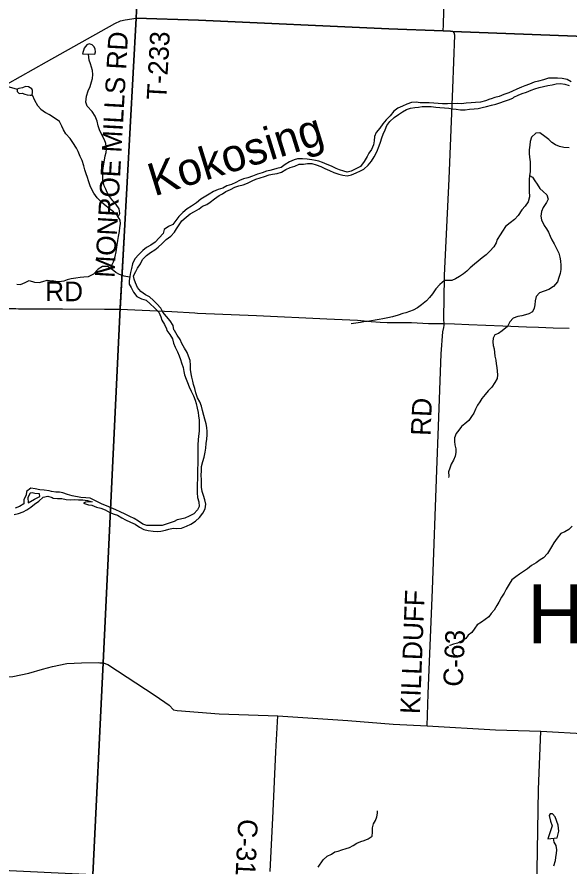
# Model space of a CAD drawing. Extents: x 1759416 to 2214760, y 252598 to 1116833.
# Drawn here: x 2002809 to 2011247, y 856869 to 869846 of the extents above; entities that cross this region are included whole.
import ezdxf

# ---------------------------------------------------------------- set-up
doc = ezdxf.new("R2010")
doc.units = 0
for name, color, linetype in [('GM_X_County_Road', 7, 'Continuous'), ('GM_X_County_Road_Text', 7, 'Continuous'), ('GM_X_Major_River', 7, 'Continuous'), ('GM_X_Major_River_Text', 7, 'Continuous'), ('GM_X_Minor_Lake', 7, 'Continuous'), ('GM_X_Minor_River', 7, 'Continuous'), ('GM_X_State_Location', 7, 'Continuous'), ('GM_X_State_Route', 7, 'Continuous'), ('GM_X_Township', 7, 'Continuous'), ('GM_X_Township_Road', 7, 'Continuous'), ('GM_X_Township_Road_Text', 7, 'Continuous'), ('GM_X_Township_Text', 7, 'Continuous')]:
    doc.layers.add(name, color=color, linetype=linetype)

msp = doc.modelspace()

# ---------------------------------------------------------------- linework, layer by layer
at = {"layer": 'GM_X_County_Road'}
for points in [[(2009323, 869634), (2009327, 869728), (2009333, 869937), (2009380, 871141), (2009401, 871508)], [(2009479, 869618), (2009472, 869626), (2009435, 869627), (2009323, 869634)], [(2009336, 865162), (2009331, 865220), (2009332, 865273), (2009338, 865524), (2009344, 865892), (2009413, 867374), (2009471, 868754), (2009503, 869566), (2009492, 869601), (2009479, 869618)], [(2000444, 865410), (2000489, 865410), (2001258, 865411), (2002106, 865391), (2002792, 865388), (2002830, 865387)], [(2002830, 865387), (2003505, 865384), (2004148, 865379), (2004179, 865379)], [(2004179, 865379), (2004185, 865379), (2004387, 865379)], [(2004387, 865379), (2004387, 865379), (2005176, 865343), (2005525, 865323), (2005570, 865321)], [(2005570, 865321), (2006468, 865283), (2007546, 865232), (2008015, 865211), (2008221, 865194), (2008359, 865180), (2008465, 865178), (2008839, 865174), (2009099, 865163), (2009336, 865162), (2009497, 865154), (2009716, 865144), (2010237, 865123), (2010595, 865109), (2010781, 865103), (2011004, 865095), (2011250, 865088)], [(2009078, 859014), (2009095, 859503), (2009158, 861095), (2009225, 862918), (2009254, 863593), (2009294, 864696), (2009317, 865034), (2009332, 865099), (2009340, 865130), (2009336, 865162)], [(2006678, 856785), (2006723, 857708), (2006764, 858614), (2006795, 859166)]]:
    msp.add_lwpolyline(points, dxfattribs=at)
at = {"layer": 'GM_X_Major_River'}
for points in [[(2011281, 868856), (2011217, 868889), (2011143, 868906), (2011072, 868910), (2011004, 868913), (2010932, 868908), (2010855, 868885), (2010783, 868865), (2010715, 868848), (2010645, 868821), (2010573, 868794), (2010522, 868774), (2010450, 868741), (2010382, 868710), (2010326, 868686), (2010249, 868659), (2010181, 868630), (2010111, 868615), (2010055, 868595), (2010037, 868588)], [(2010389, 868604), (2010403, 868618), (2010469, 868651), (2010533, 868678), (2010596, 868698), (2010666, 868729), (2010724, 868750), (2010792, 868766), (2010858, 868785), (2010924, 868800), (2010989, 868811), (2011053, 868823), (2011119, 868830), (2011183, 868821), (2011250, 868799)], [(2009606, 868520), (2009536, 868521), (2009392, 868520), (2009315, 868517), (2009247, 868522), (2009179, 868529), (2009107, 868531), (2009039, 868532), (2008971, 868535), (2008909, 868543), (2008837, 868540), (2008767, 868511), (2008700, 868482), (2008630, 868454), (2008568, 868405), (2008513, 868336), (2008450, 868273), (2008400, 868211), (2008353, 868144), (2008299, 868079), (2008276, 868021), (2008267, 867953), (2008259, 867893), (2008228, 867822), (2008189, 867762), (2008161, 867711), (2008116, 867635), (2008059, 867562), (2007989, 867527), (2007919, 867488), (2007855, 867472), (2007805, 867487), (2007739, 867510), (2007687, 867532), (2007616, 867563), (2007552, 867593), (2007480, 867624), (2007425, 867641), (2007371, 867653), (2007315, 867662), (2007245, 867672), (2007173, 867677), (2007097, 867676), (2007045, 867664), (2006973, 867631), (2006906, 867590), (2006846, 867547), (2006782, 867529), (2006728, 867514), (2006676, 867499), (2006625, 867487), (2006555, 867466), (2006483, 867443), (2006409, 867413), (2006337, 867386), (2006270, 867371), (2006208, 867346), (2006156, 867316), (2006088, 867287), (2006016, 867264), (2005953, 867231), (2005883, 867207), (2005815, 867178), (2005746, 867137), (2005618, 867060), (2005551, 867003), (2005477, 866952), (2005412, 866911), (2005346, 866858), (2005281, 866798), (2005237, 866737), (2005192, 866675), (2005126, 866642), (2005059, 866597), (2005041, 866535), (2004984, 866468), (2004923, 866405), (2004855, 866356), (2004791, 866324), (2004730, 866277), (2004670, 866216), (2004611, 866150), (2004576, 866075), (2004561, 866003), (2004545, 865940), (2004534, 865880), (2004521, 865814), (2004521, 865764), (2004552, 865710), (2004592, 865640), (2004643, 865575), (2004711, 865539), (2004782, 865518), (2004846, 865461), (2004911, 865399), (2004976, 865336), (2005008, 865262), (2005025, 865210), (2005066, 865146), (2005096, 865081), (2005101, 865054)], [(2009522, 868437), (2009589, 868429), (2009659, 868428), (2009725, 868435), (2009795, 868440), (2009857, 868446), (2009918, 868461), (2009988, 868478), (2010060, 868496), (2010128, 868513), (2010192, 868534), (2010262, 868557), (2010323, 868581), (2010389, 868604)], [(2010037, 868588), (2009971, 868564), (2009896, 868543), (2009820, 868540), (2009750, 868533), (2009676, 868526), (2009606, 868520)], [(2005215, 865054), (2005207, 865064), (2005194, 865130), (2005151, 865203), (2005094, 865269), (2005040, 865332), (2005007, 865394), (2004948, 865464), (2004896, 865513), (2004833, 865567), (2004771, 865600), (2004702, 865648), (2004650, 865713), (2004621, 865783), (2004598, 865839), (2004592, 865889), (2004625, 865955), (2004651, 866006), (2004698, 866072), (2004727, 866137), (2004789, 866199), (2004852, 866246), (2004914, 866287), (2004968, 866326), (2005027, 866386), (2005088, 866445), (2005158, 866496), (2005219, 866557), (2005249, 866607), (2005288, 866670), (2005328, 866732), (2005393, 866785), (2005457, 866838), (2005522, 866872), (2005594, 866915), (2005647, 866956), (2005709, 866982), (2005763, 867015), (2005828, 867066), (2005900, 867115), (2005952, 867143), (2006003, 867176), (2006071, 867211), (2006141, 867245), (2006199, 867264), (2006268, 867281), (2006332, 867308), (2006402, 867340), (2006462, 867367), (2006526, 867386), (2006591, 867408), (2006665, 867431), (2006717, 867444), (2006787, 867453), (2006851, 867475), (2006918, 867514), (2006986, 867545), (2007054, 867566), (2007120, 867596), (2007188, 867597), (2007252, 867606), (2007318, 867606), (2007384, 867587), (2007452, 867558), (2007513, 867532), (2007585, 867499), (2007653, 867468), (2007728, 867444), (2007790, 867427), (2007856, 867418), (2007920, 867432), (2007994, 867463), (2008059, 867494), (2008111, 867522), (2008176, 867583), (2008228, 867642), (2008271, 867708), (2008310, 867787), (2008346, 867875), (2008367, 867930), (2008388, 868000), (2008404, 868056), (2008435, 868121), (2008464, 868185), (2008510, 868250), (2008575, 868309), (2008641, 868355), (2008700, 868394), (2008764, 868431), (2008826, 868452), (2008888, 868464), (2008948, 868469), (2009004, 868475), (2009068, 868478), (2009138, 868475), (2009210, 868468), (2009274, 868462), (2009344, 868457), (2009412, 868452), (2009464, 868444), (2009522, 868437)], [(2005101, 865054), (2005147, 864992), (2005185, 864928), (2005201, 864859), (2005226, 864797), (2005262, 864727), (2005290, 864665), (2005310, 864612), (2005324, 864560), (2005348, 864490), (2005357, 864426), (2005367, 864376), (2005393, 864309), (2005415, 864257), (2005441, 864193), (2005471, 864125), (2005505, 864055), (2005532, 863988), (2005548, 863938), (2005564, 863868), (2005576, 863802), (2005584, 863752), (2005591, 863683), (2005591, 863633), (2005595, 863567), (2005595, 863515), (2005585, 863441), (2005579, 863381), (2005572, 863309), (2005572, 863254), (2005574, 863188), (2005572, 863114), (2005571, 863010), (2005567, 862940), (2005567, 862890), (2005569, 862837), (2005569, 862781), (2005565, 862711), (2005564, 862575), (2005570, 862501), (2005590, 862434), (2005592, 862366), (2005567, 862314), (2005513, 862254), (2005441, 862214), (2005375, 862188), (2005309, 862171), (2005259, 862159), (2005209, 862135), (2005152, 862115), (2005102, 862097), (2005030, 862075), (2004966, 862075), (2004916, 862072), (2004866, 862072), (2004794, 862074), (2004730, 862096), (2004664, 862142), (2004598, 862179), (2004534, 862213), (2004464, 862249), (2004386, 862284), (2004320, 862312), (2004250, 862346), (2004178, 862376), (2004110, 862401), (2004058, 862425), (2003988, 862463), (2003928, 862490), (2003860, 862496), (2003786, 862502), (2003650, 862526), (2003582, 862545), (2003510, 862571), (2003458, 862581), (2003400, 862583), (2003338, 862595), (2003302, 862604)], [(2003344, 862501), (2003362, 862493), (2003430, 862487), (2003496, 862485), (2003558, 862473), (2003620, 862464), (2003686, 862472), (2003748, 862468), (2003814, 862468), (2003886, 862458), (2003956, 862435), (2003855, 862428), (2003825, 862414), (2003904, 862392), (2003955, 862385), (2004024, 862355), (2004090, 862337), (2004158, 862312), (2004228, 862272), (2004292, 862246), (2004346, 862230), (2004412, 862191), (2004468, 862161), (2004546, 862125), (2004614, 862093), (2004682, 862050), (2004748, 862012), (2004816, 861998), (2004890, 861987), (2004956, 861983), (2005010, 861985), (2005078, 862001), (2005132, 862017), (2005198, 862035), (2005252, 862026), (2005322, 862034), (2005399, 862062), (2005467, 862096), (2005537, 862140), (2005599, 862198), (2005649, 862262), (2005684, 862328), (2005694, 862400), (2005682, 862464), (2005658, 862530), (2005640, 862595), (2005631, 862661), (2005627, 862723), (2005627, 862773), (2005625, 862841), (2005627, 862911), (2005631, 862976), (2005650, 863050), (2005672, 863120), (2005684, 863192), (2005694, 863256), (2005701, 863326), (2005709, 863392), (2005717, 863460), (2005715, 863511), (2005711, 863571), (2005699, 863625), (2005680, 863697), (2005666, 863757), (2005646, 863830), (2005628, 863898), (2005602, 863962), (2005570, 864024), (2005545, 864101), (2005529, 864167), (2005507, 864231), (2005495, 864281), (2005481, 864341), (2005471, 864391), (2005462, 864456), (2005462, 864524), (2005456, 864596), (2005432, 864664), (2005408, 864716), (2005371, 864785), (2005331, 864853), (2005301, 864917), (2005255, 864985), (2005215, 865054)], [(2003302, 862604), (2003224, 862612), (2003156, 862621), (2003086, 862635), (2003022, 862643), (2002952, 862591), (2002950, 862539), (2002914, 862471), (2002912, 862404), (2002848, 862364), (2002782, 862341)], [(2003012, 862569), (2002976, 862503), (2002980, 862420), (2003078, 862474)], [(2003078, 862474), (2003156, 862516), (2003152, 862558), (2003082, 862565), (2003040, 862575), (2003012, 862569)], [(2002768, 862244), (2002830, 862258), (2002904, 862284), (2002958, 862312), (2003022, 862356), (2003076, 862398), (2003142, 862448), (2003210, 862506), (2003278, 862524), (2003344, 862501)]]:
    msp.add_lwpolyline(points, dxfattribs=at)
at = {"layer": 'GM_X_Minor_Lake'}
for points in [[(2003997, 869278), (2004007, 869312), (2004005, 869354), (2003989, 869388), (2003959, 869418), (2003914, 869434), (2003878, 869420), (2003837, 869368), (2003811, 869280)], [(2003811, 869280), (2003997, 869278)], [(2003048, 868691), (2003047, 868721), (2003035, 868749), (2002987, 868777), (2002939, 868784), (2002895, 868764), (2002835, 868752), (2002810, 868740), (2002814, 868706), (2002844, 868678), (2002888, 868680), (2002930, 868664), (2002966, 868655), (2003012, 868651)], [(2003012, 868651), (2003029, 868650), (2003043, 868654), (2003048, 868691)], [(2011067, 857302), (2011093, 857402), (2011079, 857495), (2011036, 857619), (2010996, 857669), (2010960, 857665), (2010946, 857639), (2010966, 857557), (2010989, 857481), (2010925, 857284)], [(2010925, 857284), (2011067, 857302)]]:
    msp.add_lwpolyline(points, dxfattribs=at)
at = {"layer": 'GM_X_Minor_River'}
for points in [[(2004355, 866791), (2004381, 866843), (2004371, 866913), (2004324, 866981), (2004274, 867037), (2004230, 867099), (2004189, 867165), (2004165, 867215), (2004141, 867267), (2004123, 867355), (2004120, 867435), (2004122, 867497), (2004134, 867601), (2004144, 867655), (2004155, 867726), (2004171, 867776), (2004179, 867826), (2004167, 867910), (2004146, 867970), (2004112, 868034), (2004072, 868120), (2004049, 868184), (2004033, 868254), (2004005, 868330), (2003956, 868402), (2003884, 868482), (2003862, 868546), (2003869, 868634), (2003899, 868719), (2003925, 868781), (2003949, 868853), (2003961, 868905), (2003968, 868969), (2003962, 869026), (2003948, 869080), (2003932, 869132), (2003913, 869184), (2003904, 869279)], [(2001828, 869053), (2001891, 869015), (2001949, 868988), (2002073, 868939), (2002131, 868907), (2002213, 868888), (2002291, 868898), (2002351, 868900), (2002421, 868873), (2002495, 868831), (2002571, 868802), (2002627, 868788), (2002689, 868777), (2002810, 868740)], [(2003042, 868654), (2003078, 868572), (2003123, 868494), (2003175, 868438), (2003247, 868385), (2003300, 868353)], [(2004238, 866004), (2004252, 866040), (2004282, 866101), (2004309, 866185), (2004327, 866257), (2004339, 866361), (2004351, 866428), (2004360, 866492), (2004374, 866568), (2004382, 866626), (2004390, 866686), (2004385, 866742), (2004345, 866806), (2004283, 866866), (2004225, 866914), (2004172, 866954), (2004104, 867012), (2004034, 867084), (2003985, 867152), (2003951, 867210), (2003929, 867266), (2003904, 867342), (2003888, 867392), (2003868, 867448), (2003846, 867512), (2003829, 867572), (2003803, 867652), (2003777, 867712), (2003742, 867792), (2003716, 867842), (2003664, 867928), (2003620, 867990), (2003553, 868060), (2003519, 868122), (2003495, 868178), (2003460, 868246), (2003300, 868353)], [(2011249, 867846), (2011167, 867850), (2011102, 867868), (2011038, 867890), (2010986, 867929), (2010936, 867971), (2010877, 868019), (2010803, 868075), (2010739, 868071), (2010675, 868009), (2010651, 867940), (2010646, 867884), (2010640, 867814), (2010638, 867758), (2010642, 867704), (2010651, 867630), (2010653, 867556), (2010653, 867481), (2010645, 867423), (2010640, 867359), (2010638, 867309), (2010640, 867237), (2010640, 867185), (2010643, 867099), (2010621, 867020), (2010575, 866954), (2010525, 866898), (2010470, 866811), (2010414, 866749), (2010348, 866699), (2010274, 866642), (2010228, 866572), (2010194, 866518), (2010148, 866446), (2010131, 866393), (2010099, 866335), (2010039, 866267), (2009981, 866211), (2009921, 866166), (2009857, 866114), (2009801, 866070), (2009734, 866013), (2009684, 865961), (2009632, 865921), (2009572, 865878), (2009512, 865844), (2009454, 865816), (2009394, 865818), (2009344, 865816), (2009270, 865759), (2009212, 865689), (2009160, 865614), (2009116, 865556), (2009071, 865506), (2008991, 865446), (2008929, 865401), (2008863, 865367), (2008811, 865343), (2008755, 865324), (2008705, 865312), (2008633, 865290), (2008551, 865264), (2008475, 865249), (2008403, 865233), (2008345, 865223), (2008283, 865211), (2008227, 865200), (2008161, 865190), (2008111, 865184), (2008058, 865176), (2007988, 865164), (2007918, 865155)], [(2010645, 867421), (2010688, 867397), (2010726, 867343), (2010760, 867291), (2010800, 867223), (2010853, 867179), (2010907, 867128), (2010929, 867059), (2010905, 867009), (2010850, 866933), (2010824, 866873), (2010818, 866803), (2010828, 866746), (2010869, 866660), (2010905, 866608), (2010935, 866556), (2010957, 866494), (2010982, 866442), (2011018, 866376), (2011058, 866308), (2011091, 866234), (2011109, 866174), (2011119, 866118), (2011121, 866046), (2011120, 865986), (2011110, 865924), (2011092, 865864), (2011070, 865797), (2011008, 865725), (2010939, 865681), (2010865, 865654), (2010797, 865628), (2010745, 865576), (2010729, 865508), (2010725, 865448), (2010715, 865397), (2010687, 865339), (2010632, 865307), (2010580, 865293), (2010525, 865280), (2010467, 865270), (2010395, 865242), (2010342, 865188), (2010306, 865117)], [(2004531, 865868), (2004445, 865885), (2004377, 865909), (2004322, 865941), (2004264, 865988), (2004190, 866032), (2004118, 866034), (2004050, 865990), (2003976, 865917), (2003898, 865873), (2003832, 865867), (2003776, 865862), (2003706, 865854), (2003638, 865844), (2003576, 865826), (2003524, 865810), (2003452, 865799), (2003400, 865803), (2003348, 865815)], [(2002808, 865764), (2002860, 865759), (2002932, 865789), (2002996, 865817), (2003074, 865792), (2003146, 865786), (2003206, 865803), (2003268, 865821), (2003348, 865815)], [(2010306, 865117), (2010226, 865049), (2010168, 865008), (2010114, 864986), (2010088, 864936), (2010085, 864882), (2010089, 864826), (2010101, 864776), (2010107, 864718), (2010115, 864663), (2010127, 864601), (2010135, 864545), (2010143, 864491), (2010151, 864433), (2010153, 864375), (2010147, 864321), (2010114, 864260), (2010068, 864188), (2010010, 864134), (2009964, 864078), (2009916, 864013), (2009884, 863963), (2009846, 863911), (2009820, 863851), (2009792, 863789), (2009754, 863739), (2009716, 863680), (2009656, 863628), (2009602, 863586), (2009562, 863532), (2009522, 863478), (2009498, 863415), (2009499, 863359), (2009503, 863305), (2009515, 863245), (2009517, 863187), (2009509, 863135), (2009483, 863072), (2009447, 863012), (2009423, 862952), (2009405, 862894), (2009409, 862826), (2009407, 862808)], [(2011296, 862063), (2011244, 862015), (2011182, 861975), (2011120, 861949), (2011064, 861881), (2011014, 861808), (2010980, 861750), (2010948, 861698), (2010916, 861644), (2010856, 861582), (2010804, 861550), (2010744, 861505), (2010676, 861463), (2010610, 861413), (2010552, 861369), (2010488, 861331), (2010436, 861290), (2010372, 861242), (2010332, 861178), (2010287, 861100), (2010257, 861042), (2010217, 860979), (2010173, 860901), (2010143, 860851), (2010105, 860781), (2010059, 860731), (2010021, 860676), (2009965, 860638), (2009911, 860594), (2009845, 860554), (2009809, 860504), (2009763, 860440), (2009707, 860397), (2009669, 860347), (2009599, 860303), (2009541, 860277), (2009479, 860261), (2009423, 860241), (2009423, 860243)], [(2007413, 856854), (2007489, 856966), (2007549, 857018), (2007615, 857048), (2007669, 857084), (2007719, 857097), (2007775, 857115), (2007841, 857135), (2007891, 857151), (2007949, 857183), (2008003, 857219), (2008063, 857243), (2008117, 857261), (2008177, 857283), (2008239, 857324), (2008243, 857386), (2008245, 857454), (2008259, 857516), (2008287, 857566), (2008311, 857622), (2008320, 857677), (2008318, 857713)], [(2011004, 857294), (2011013, 857234), (2011043, 857184), (2011055, 857118), (2011053, 857059), (2011041, 857005), (2011037, 856947), (2011012, 856867)]]:
    msp.add_lwpolyline(points, dxfattribs=at)
at = {"layer": 'GM_X_State_Route'}
for points in [[(1999236, 860980), (1999241, 860976), (1999579, 860693), (1999693, 860619), (1999791, 860579), (1999891, 860539), (2001171, 860278), (2002083, 859839), (2002239, 859788), (2002493, 859752), (2002747, 859765), (2002988, 859818), (2003199, 859877)], [(2003199, 859877), (2003350, 859920), (2003572, 859965), (2003793, 859975), (2004051, 859978), (2004073, 859973), (2004125, 859974), (2004199, 859949), (2004921, 859476), (2005135, 859328), (2005200, 859257), (2005258, 859247), (2005901, 859193), (2006795, 859166), (2007866, 859093), (2008557, 859039), (2009078, 859014), (2010125, 858951), (2010815, 858930), (2012254, 858849)]]:
    msp.add_lwpolyline(points, dxfattribs=at)
at = {"layer": 'GM_X_Township'}
for points in [[(2015533, 869394), (2009472, 869626), (2009435, 869627), (2009323, 869634), (2008493, 869663), (2005582, 869797), (2004631, 869830), (2004641, 870054), (2004694, 871221), (2004839, 874118), (2004865, 874840), (2004927, 875992), (2004982, 876962), (2004981, 877025), (2004971, 877073), (2005010, 877802), (2005039, 878117), (2005059, 878425), (2005076, 878623), (2005114, 879912), (2005203, 881312), (2005267, 882814), (2005306, 883398), (2005439, 886067)], [(1992605, 870569), (1994920, 870479), (1995113, 870471), (1995355, 870468), (1995405, 870464), (1995466, 870455), (1997362, 870362), (1997798, 870346), (1998295, 870325), (1998468, 870317), (1999895, 870251), (2000935, 870208), (2004641, 870054), (2004631, 869830), (2004447, 866486), (2004388, 865398), (2004125, 859974), (2003969, 856734), (2000253, 856911), (1997119, 857079), (1997089, 857058), (1996543, 857095), (1993563, 857259), (1990529, 857428)], [(2014123, 842824), (2010315, 842932), (2008046, 842997), (2007679, 843011), (2004076, 843164), (2003536, 843173), (2003448, 843183), (2003402, 843192), (2003345, 843225), (2003490, 846373), (2003685, 851167), (2003906, 855077), (2003969, 856734), (2004125, 859974), (2004388, 865398), (2004447, 866486), (2004631, 869830), (2005582, 869797), (2008493, 869663), (2009323, 869634), (2009435, 869627), (2009472, 869626), (2015533, 869394)]]:
    msp.add_lwpolyline(points, dxfattribs=at)
at = {"layer": 'GM_X_Township_Road'}
for points in [[(2004641, 870054), (2004631, 869830)], [(1999764, 866209), (1999792, 866273), (1999868, 866388), (1999957, 866519), (2000000, 866641), (2000088, 866865), (2000216, 867165), (2000407, 867504), (2000511, 867638), (2000722, 867834), (2000851, 867921), (2001252, 868129), (2002253, 868600), (2002458, 868711), (2003259, 869159), (2004304, 869746), (2004392, 869785), (2004464, 869801), (2004631, 869830)], [(2004631, 869830), (2004447, 866486), (2004387, 865379)], [(2004631, 869830), (2004631, 869830), (2005582, 869797), (2006951, 869734)], [(2006951, 869734), (2008493, 869663), (2009323, 869634)], [(2010610, 851505), (2010640, 852363), (2010688, 853843), (2010749, 856179), (2010778, 858039), (2010815, 858930)]]:
    msp.add_lwpolyline(points, dxfattribs=at)

# ---------------------------------------------------------------- texts
at = {"layer": 'GM_X_County_Road_Text'}
for s, rotation, p in [('RD', 359.5063, (2003238, 865505)), ('RD', 87.5323, (2009129, 863440)), ('KILLDUFF', 87.7266, (2008967, 859188)), ('C-63', 87.5998, (2009623, 859605)), ('C-31', 267.2576, (2006192, 857593))]:
    msp.add_text(s, height=300, rotation=rotation, dxfattribs=at).set_placement(p)
at = {"layer": 'GM_X_Major_River_Text'}
msp.add_text('Kokosing', height=500, rotation=17.2306, dxfattribs=at).set_placement((2004906, 867102))
at = {"layer": 'GM_X_State_Location'}
msp.add_text('229', height=1, rotation=0, dxfattribs=at).set_placement((2009560, 858775))
for s in ['s', 'r']:
    msp.add_text(s, height=1, dxfattribs=at).set_placement((2009913, 858848))
at = {"layer": 'GM_X_Township_Road_Text'}
for s, rotation, p in [('MONROE MILLS RD', 86.7996, (2004298, 865854)), ('T-233', 86.8979, (2005090, 868571))]:
    msp.add_text(s, height=300, rotation=rotation, dxfattribs=at).set_placement(p)
at = {"layer": 'GM_X_Township_Text'}
msp.add_text('HARRISON', height=900, rotation=0, dxfattribs=at).set_placement((2010610, 860273))

doc.saveas('drawing.dxf')
